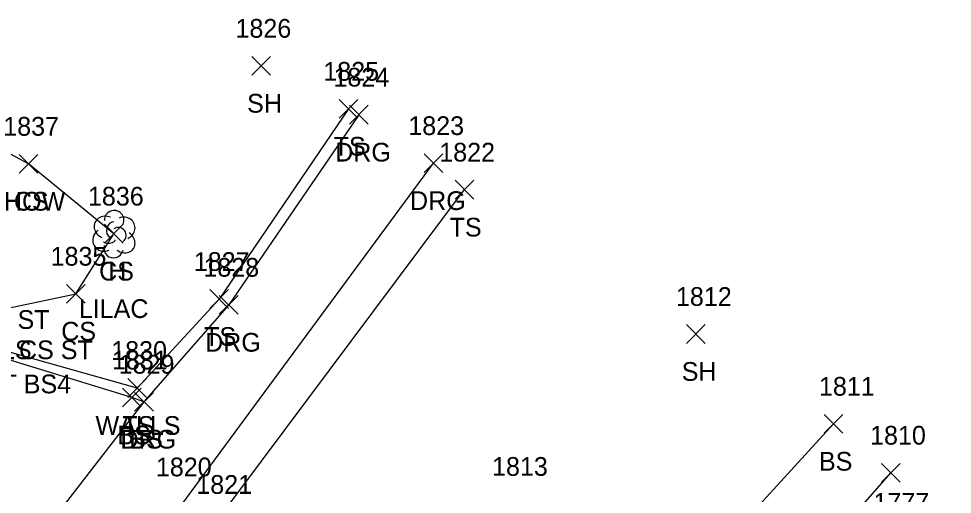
# Model space of a CAD drawing. Extents: x 1499292 to 1501024, y 534584 to 538043.
# Drawn here: x 1500027.5 to 1500127.1, y 537739.8 to 537790.6 of the extents above; entities that cross this region are included whole.
import ezdxf

# ---------------------------------------------------------------- set-up
doc = ezdxf.new("R2010")
doc.units = 0
for name, color, linetype in [('L_A', 7, 'Continuous'), ('L_C', 7, 'Continuous'), ('L_I', 7, 'Continuous'), ('L_TIC', 7, 'Continuous'), ('LBC', 7, 'Continuous'), ('LELB', 7, 'Continuous'), ('LTD', 7, 'Continuous'), ('LWS', 7, 'Continuous'), ('R_A', 7, 'Continuous'), ('R_I', 7, 'Continuous'), ('R_TIC', 7, 'Continuous'), ('RDG', 7, 'Continuous')]:
    doc.layers.add(name, color=color, linetype=linetype)

msp = doc.modelspace()

# ---------------------------------------------------------------- linework, layer by layer
at = {"layer": 'L_TIC'}
for points in [[(1500052.4, 537784.528), (1500054.4, 537786.528)], [(1500054.4, 537784.528), (1500052.4, 537786.528)], [(1500061.714, 537779.937), (1500063.714, 537781.937)], [(1500063.714, 537779.937), (1500061.714, 537781.937)], [(1500027.567, 537774.069), (1500029.567, 537776.069)], [(1500029.567, 537774.069), (1500027.567, 537776.069)], [(1500027.567, 537774.069), (1500029.567, 537776.069)], [(1500029.567, 537774.069), (1500027.567, 537776.069)], [(1500074.087, 537771.308), (1500076.087, 537773.308)], [(1500076.087, 537771.308), (1500074.087, 537773.308)], [(1500036.66, 537766.611), (1500038.66, 537768.611)], [(1500038.66, 537766.611), (1500036.66, 537768.611)], [(1500032.62, 537760.197), (1500034.62, 537762.197)], [(1500034.62, 537760.197), (1500032.62, 537762.197)], [(1500047.898, 537759.636), (1500049.898, 537761.636)], [(1500049.898, 537759.636), (1500047.898, 537761.636)], [(1500098.771, 537755.905), (1500100.771, 537757.905)], [(1500100.771, 537755.905), (1500098.771, 537757.905)], [(1500039.176, 537750.139), (1500041.176, 537752.139)], [(1500041.176, 537750.139), (1500039.176, 537752.139)], [(1500039.176, 537750.139), (1500041.176, 537752.139)], [(1500041.176, 537750.139), (1500039.176, 537752.139)], [(1500038.597, 537749.115), (1500040.597, 537751.115)], [(1500040.597, 537749.115), (1500038.597, 537751.115)], [(1500039.89, 537748.673), (1500041.89, 537750.673)], [(1500041.89, 537748.673), (1500039.89, 537750.673)], [(1500113.46, 537746.319), (1500115.46, 537748.319)], [(1500115.46, 537746.319), (1500113.46, 537748.319)], [(1500119.57, 537741.098), (1500121.57, 537743.098)], [(1500121.57, 537741.098), (1500119.57, 537743.098)]]:
    msp.add_lwpolyline(points, dxfattribs=at)
at = {"layer": 'LBC'}
msp.add_lwpolyline([(1500028.567, 537775.069), (1500012.836, 537783.494)], dxfattribs=at)
at = {"layer": 'LELB'}
for points in [[(1500062.714, 537780.937), (1500048.898, 537760.636), (1500040.176, 537751.139)], [(1500024.296, 537759.216), (1500033.62, 537761.197), (1500037.66, 537767.611), (1500028.567, 537775.069)], [(1500034.975, 537718.652), (1500048.597, 537736.843), (1500075.087, 537772.308)], [(1500040.89, 537749.673), (1500039.597, 537750.115), (1500021.818, 537755.572), (1500019.058, 537757.497), (1500006.738, 537764.649), (1500001.694, 537767.196), (1500001.185, 537767.928)], [(1500127.131, 537730.887), (1500107.857, 537707.819), (1500088.099, 537686.601), (1500068.646, 537671.419), (1500059.362, 537663.71), (1500048.92, 537663.954), (1500044.957, 537669.403), (1500047.546, 537678.657), (1500065.614, 537698.373), (1500088.483, 537718.89), (1500114.46, 537747.319)], [(1500124.066, 537733.12), (1500104.854, 537710.666), (1500085.99, 537688.969), (1500067.489, 537673.656), (1500059.432, 537665.884), (1500053.115, 537667.182), (1500053.524, 537674.362), (1500071.576, 537690.906), (1500095.968, 537713.937), (1500120.57, 537742.098)]]:
    msp.add_lwpolyline(points, dxfattribs=at)
at = {"layer": 'LTD'}
msp.add_line((1500037.66, 537767.611), (1500037.66, 537767.611), dxfattribs=at)
msp.add_line((1500037.66, 537767.611), (1500037.66, 537767.611), dxfattribs=at)
msp.add_arc((1500037.707, 537769.045), 1.047, 335.52715, 180.95627, dxfattribs=at)
for centre, major_axis, ratio, start_param, end_param in [((1500036.868, 537768.278), (1.21, -0.512), 0.895232, 1.570796, 4.712389), ((1500038.702, 537768.195), (-1.141, -0.483), 0.949671, 1.570796, 4.712389), ((1500037.452, 537768.069), (-0.208, -0.792), 0.645439, 3.141593, 6.283185), ((1500036.577, 537766.903), (0.584, -1.042), 0.959034, 3.141593, 6.283185), ((1500038.16, 537767.445), (-0.5, 0.667), 0.989748, 3.141593, 6.283185), ((1500038.66, 537766.778), (-1.09, 0.792), 0.841452, 1.570796, 4.712389), ((1500037.202, 537766.861), (-0.625, -0.083), 0.423636, 0, 3.141593), ((1500037.66, 537766.111), (0.265, 1.061), 0.942809, 1.570796, 4.712389)]:
    msp.add_ellipse(centre, major_axis=major_axis, ratio=ratio, start_param=start_param, end_param=end_param, dxfattribs=at)
at = {"layer": 'LWS'}
msp.add_lwpolyline([(1500040.176, 537751.139), (1500022.336, 537756.133), (1500024.296, 537759.216)], dxfattribs=at)
at = {"layer": 'R_TIC'}
for points in [[(1500062.799, 537779.312), (1500064.799, 537781.312)], [(1500064.799, 537779.312), (1500062.799, 537781.312)], [(1500070.784, 537774.136), (1500072.784, 537776.136)], [(1500072.784, 537774.136), (1500070.784, 537776.136)], [(1500048.926, 537759.02), (1500050.926, 537761.02)], [(1500050.926, 537759.02), (1500048.926, 537761.02)], [(1500039.89, 537748.673), (1500041.89, 537750.673)], [(1500041.89, 537748.673), (1500039.89, 537750.673)]]:
    msp.add_lwpolyline(points, dxfattribs=at)
at = {"layer": 'RDG'}
for points in [[(1500063.799, 537780.312), (1500049.926, 537760.02), (1500040.89, 537749.673), (1500021.784, 537724.996), (1500010.572, 537724.396), (1499997.374, 537717.943), (1500005.783, 537701.6), (1500015.338, 537685.643), (1500022.036, 537662.579)], [(1500051.012, 537655.067), (1500050.29, 537657.354), (1500038.144, 537671.203), (1500031.021, 537686.43), (1500030.594, 537703.516), (1500034.975, 537718.652), (1500044.939, 537738.713), (1500071.784, 537775.136)]]:
    msp.add_lwpolyline(points, dxfattribs=at)

# ---------------------------------------------------------------- texts
at = {"layer": 'L_A'}
for s, p in [('SH', (1500051.889, 537780.528)), ('TS', (1500061.124, 537775.937)), ('HOW', (1500025.953, 537770.069)), ('CS', (1500027.008, 537770.069)), ('TS', (1500073.496, 537767.308)), ('CS', (1500036.101, 537762.611)), ('H', (1500037.093, 537762.611)), ('STPS WALLS4 ST', (1500008.374, 537757.447)), ('CS', (1500032.061, 537756.197)), ('TS', (1500047.307, 537755.636)), ('WALLS4 STPS CS ST', (1500008.525, 537754.216)), ('WALLS', (1500019.84, 537754.216)), ('SH', (1500098.259, 537751.905)), ('SHRUB STPS ST BS4', (1500006.07, 537750.572)), ('WALLS', (1500035.719, 537746.139)), ('TS', (1500038.585, 537746.139)), ('BS', (1500038.038, 537745.115)), ('BS', (1500039.331, 537744.673)), ('BS', (1500112.901, 537742.319))]:
    msp.add_text(s, height=2, dxfattribs=at).set_placement(p)
at = {"layer": 'L_C'}
msp.add_text('LILAC', height=2, dxfattribs=at).set_placement((1500033.936, 537758.611))
at = {"layer": 'L_I'}
for s, p in [('1826', (1500050.652, 537788.528)), ('1825', (1500060.021, 537783.937)), ('1837', (1500025.874, 537778.069)), ('1837', (1500025.874, 537778.069)), ('1822', (1500072.394, 537775.308)), ('1836', (1500034.912, 537770.611)), ('1836', (1500034.912, 537770.611)), ('1835', (1500030.927, 537764.197)), ('1827', (1500046.205, 537763.636)), ('1812', (1500097.645, 537759.905)), ('1830', (1500037.396, 537754.139)), ('1830', (1500037.396, 537754.139)), ('1831', (1500037.471, 537753.115)), ('1829', (1500038.189, 537752.673)), ('1811', (1500112.901, 537750.319)), ('1810', (1500118.357, 537745.098)), ('1813', (1500078.025, 537741.766)), ('1821', (1500046.471, 537739.843)), ('1777', (1500118.716, 537737.934))]:
    msp.add_text(s, height=2, dxfattribs=at).set_placement(p)
at = {"layer": 'R_A'}
for p in [(1500061.287, 537775.312), (1500069.272, 537770.136), (1500047.414, 537755.02), (1500038.378, 537744.673)]:
    msp.add_text('DRG', height=2, dxfattribs=at).set_placement(p)
at = {"layer": 'R_I'}
for s, p in [('1824', (1500061.106, 537783.312)), ('1823', (1500069.091, 537778.136)), ('1828', (1500047.233, 537763.02)), ('1829', (1500038.189, 537752.673)), ('1820', (1500042.16, 537741.713))]:
    msp.add_text(s, height=2, dxfattribs=at).set_placement(p)

doc.saveas('drawing.dxf')
